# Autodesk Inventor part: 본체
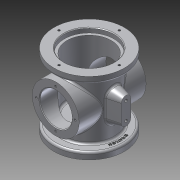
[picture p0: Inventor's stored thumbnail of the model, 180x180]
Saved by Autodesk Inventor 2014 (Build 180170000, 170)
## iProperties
Created: 2018-02
Part Number: 본체
Material: 알루미늄 6061
Document SubType Name: Modeling
Designer: OA65
Density: 2.71 g/cm^3
Appearance: 알루미늄 - 평지
Author: OA65
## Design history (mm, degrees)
sketch "스케치1"
  geometry: C1 r 33 at (0, 0); C2 r 38 at (0, 0); 1 further point
  constraints: 2 centre point, 2 coincident
  dimensions: "d0" = 66 diameter of C1; "d1" = 76 diameter of C2
extrude "돌출1" new body sketch "스케치1" distance "d2" = 108; taper "d3" = 0 deg
sketch "스케치2"
  geometry: C1 r 38 at (0, 0) reference; C2 r 52.5 at (0, 0)
  constraints: 1 centre point, 1 coincident
  dimensions: "d4" = 105 diameter of C2
extrude "돌출2" join sketch "스케치2" distance "d5" = 10; taper "d6" = 0 deg
sketch "스케치3"
  geometry: C1 r 38 at (0, 0) reference; C2 r 52.5 at (0, 0)
  constraints: 1 centre point, 1 coincident
  dimensions: "d8" = 105 diameter of C2
extrude "돌출3" join sketch "스케치3" distance "d9" = 10; taper "d10" = 0 deg
sketch "스케치4"
  geometry: C1 r 52.5 at (0, 0) reference; C2 r 37 at (0, 0)
  constraints: 1 centre point, 1 coincident
  dimensions: "d11" = 74 diameter of C2
extrude "돌출4" cut sketch "스케치4" distance "d12" = 7; taper "d13" = 0 deg
sketch "스케치5"
  geometry: C1 r 37 at (0, 0) reference; C2 r 33 at (0, 0)
  constraints: 1 centre point, 1 coincident
  dimensions: "d14" = 66 diameter of C2
extrude "돌출5" cut sketch "스케치5" distance "d15" = 79; taper "d16" = 0 deg
sketch "스케치6"
  geometry: C1 r 52.5 at (0, 0) reference; C2 r 34 at (0, 0)
  constraints: 1 centre point, 1 coincident
  dimensions: "d17" = 68 diameter of C2
extrude "돌출6" cut sketch "스케치6" distance "d18" = 16; taper "d19" = 0 deg
sketch "스케치7"
  geometry: L1 (38, 10)-(52.5, 10) reference; L2 (52.5, 10)-(52.5, 0) reference; L3 (52.5, 0)-(37, 0) reference; L4 (37, 0)-(37, 7) reference; L5 (37, 7)-(33, 7) reference; L6 (33, 7)-(33, 86) reference; L7 (33, 86)-(-33, 86) reference; L8 (-33, 86)-(-33, 7) reference; L9 (-33, 7)-(-37, 7) reference; L10 (-37, 7)-(-37, 0) reference; L11 (-37, 0)-(-52.5, 0) reference; L12 (-52.5, 0)-(-52.5, 10) reference; L13 (-52.5, 10)-(-38, 10) reference; L14 (-38, 10)-(-38, 98) reference; L15 (-38, 98)-(-52.5, 98) reference; L16 (-52.5, 98)-(-52.5, 108) reference; L17 (-52.5, 108)-(-34, 108) reference; L18 (-34, 108)-(-34, 92) reference; L19 (-34, 92)-(34, 92) reference; L20 (34, 92)-(34, 108) reference; L21 (34, 108)-(52.5, 108) reference; L22 (52.5, 108)-(52.5, 98) reference; L23 (52.5, 98)-(38, 98) reference; L24 (38, 98)-(38, 10) reference; L25 (0, 108)-(0, 54); C1 r 24 at (0, 54); C2 r 35 at (0, 54); 1 further point
  constraints: 2 centre point, 2 coincident, 2 end point, 1 parallel
  dimensions: "d20" = 54 distance of L25.start L25.end; "d21" = 48 diameter of C1; "d22" = 70 diameter of C2
extrude "돌출7" join sketch "스케치7" stored distance "d23" = 100; taper "d24" = 0 deg
sketch "스케치8"
  geometry: C1 r 24 at (0, 0) reference; C2 r 35 at (0, 0) reference; C3 r 24 at (0, 0); 1 further point
  constraints: 1 centre point, 1 coincident, 1 concentric
extrude "돌출8" cut sketch "스케치8" distance "d25" = 150; taper "d26" = 0 deg
sketch "스케치9"
  geometry: C1 r 37 at (0, 0) reference; C2 r 52.5 at (0, 0) reference; C3 r 37 at (0, 0)
  constraints: 1 centre point, 1 coincident, 1 concentric
extrude "돌출9" cut sketch "스케치9" distance "d27" = 86; taper "d28" = 0 deg
sketch "스케치10"
  geometry: C1 r 37 at (0, 0) reference; C2 r 33 at (0, 0)
  constraints: 1 centre point, 1 coincident
  dimensions: "d29" = 66 diameter of C2
extrude "돌출10" join sketch "스케치10" distance "d30" = 79; taper "d31" = 0 deg
sketch "스케치11"
  geometry: C1 r 24 at (0, 0) reference; C2 r 35 at (0, 0) reference; C3 r 24 at (0, 0); 1 further point
  constraints: 1 centre point, 1 coincident, 1 concentric
extrude "돌출11" cut sketch "스케치11" distance "d32" = 150; taper "d33" = 0 deg
sketch "스케치12"
  geometry: C1 r 33 at (0, 0) reference; C2 r 5 at (0, 0)
  constraints: 1 centre point, 1 coincident
  dimensions: "d34" = 10 diameter of C2
extrude "돌출12" cut sketch "스케치12" distance "d35" = 14; taper "d36" = 0 deg
node "작업 평면1"
fillet "모깎기1" dims "d50" = 3
fillet "모깎기2" dims "d51" = 3
chamfer "모따기1" distance "d52" = 1; stored, may be unused: second distance "d53" = 2, angle "d54" = 45 deg
sketch "스케치17" dims "d64" = 90
  geometry: C1 r 38 at (0, 0) reference; 2 further points
  constraints: 1 coincident, 1 vertical alignment, 2 other
hole "구멍2" sketch "스케치17" at (0, 45) diameter "d65" = 3.242; stored, may be unused: countersink angle "d69" = 90 deg, drill point angle "d71" = 118 deg; dims "d66" = 4, "d67" = 4, "d68" = 2, "d70" = 6
sketch "스케치18" dims "d75" = 58
  geometry: C1 r 25 at (0, 0) reference; 3 further points
  constraints: 1 coincident, 1 vertical alignment, 2 other
hole "구멍3" sketch "스케치18" at (0, 29) diameter "d76" = 3.242; stored, may be unused: countersink angle "d80" = 90 deg, drill point angle "d82" = 118 deg; dims "d77" = 4, "d78" = 4, "d79" = 2, "d81" = 6
node "작업 평면2"
sketch "스케치19"
  geometry: L1 (-31, 92)-(-5, 92) reference; L2 (-5, 92)-(-5, 86) reference; L3 (-5, 86)-(-30, 86) reference; L4 (-33, 83)-(-33, 7) reference; L5 (-33, 7)-(-37, 7) reference; L6 (-37, 7)-(-37, 1) reference; L7 (-37, 1)-(-38, 0) reference; L8 (-38, 0)-(-43.379, 0) reference; L9 (-43.379, 0)-(-43.379, 6) reference; L10 (-43.379, 6)-(-45, 6.974) reference; L11 (-45, 6.974)-(-46.621, 6) reference; L12 (-46.621, 6)-(-46.621, 0) reference; L13 (-46.621, 0)-(-52.5, 0) reference; L14 (-52.5, 0)-(-52.5, 7) reference; L15 (-49.5, 10)-(-41, 10) reference; L16 (-38, 13)-(-38, 95) reference; L17 (-41, 98)-(-49.5, 98) reference; L18 (-52.5, 101)-(-52.5, 108) reference; L19 (-52.5, 108)-(-34, 108) reference; L20 (-34, 108)-(-34, 95) reference; L21 (34, 95)-(34, 108) reference; L22 (34, 108)-(52.5, 108) reference; L23 (52.5, 108)-(52.5, 101) reference; L24 (49.5, 98)-(41, 98) reference; L25 (38, 95)-(38, 13) reference; L26 (41, 10)-(49.5, 10) reference; L27 (52.5, 7)-(52.5, 0) reference; L28 (52.5, 0)-(46.621, 0) reference; L29 (46.621, 0)-(46.621, 6) reference; L30 (46.621, 6)-(45, 6.974) reference; L31 (45, 6.974)-(43.379, 6) reference; L32 (43.379, 6)-(43.379, 0) reference; L33 (43.379, 0)-(38, 0) reference; L34 (38, 0)-(37, 1) reference; L35 (37, 1)-(37, 7) reference; L36 (37, 7)-(33, 7) reference; L37 (33, 7)-(33, 83) reference; L38 (30, 86)-(5, 86) reference; L39 (5, 86)-(5, 92) reference; L40 (5, 92)-(31, 92) reference; L41 (0, 54)-(55, 54); L42 (55, 41)-(55, 34); L43 (55, 34)-(38, 29.445); L44 (55, 67)-(55, 74); L45 (55, 74)-(38, 78.555); L46 (55, 41)-(38, 41); L47 (55, 67)-(38, 67); A1 r 3 centre (-31, 95) between (-34, 95) and (-31, 92) reference; A2 r 3 centre (-30, 83) between (-30, 86) and (-33, 83) reference; A3 r 3 centre (-49.5, 7) between (-49.5, 10) and (-52.5, 7) reference; A4 r 3 centre (-41, 13) between (-41, 10) and (-38, 13) reference; A5 r 3 centre (-41, 95) between (-38, 95) and (-41, 98) reference; A6 r 3 centre (-49.5, 101) between (-52.5, 101) and (-49.5, 98) reference; A7 r 3 centre (31, 95) between (31, 92) and (34, 95) reference; A8 r 3 centre (49.5, 101) between (49.5, 98) and (52.5, 101) reference; A9 r 3 centre (41, 95) between (41, 98) and (38, 95) reference; A10 r 3 centre (41, 13) between (38, 13) and (41, 10) reference; A11 r 3 centre (49.5, 7) between (52.5, 7) and (49.5, 10) reference; A12 r 3 centre (30, 83) between (33, 83) and (30, 86) reference; 2 further points
  constraints: 14 end point, 4 point on line, 3 perpendicular, 1 collinear, 1 parallel, 1 other
  dimensions: "d87" = 55 distance of L41.start L41.end; "d88" = 20 distance of L41.end L42.end; "d89" = 20 distance of L41.end L44.end; "d90" = 13 distance of L42.start L41.end; "d91" = 13 distance of L44.start L41.end
  node "절단 모서리 투영4"
revolve "회전3" stored, may be unused: angle "d92" = 90 deg
revolve "회전4" stored, may be unused: angle "d93" = 90 deg
sketch "스케치20"
  geometry: L1 (-7, 0)-(-7, -26); L2 (7, 0)-(7, -26); A1 r 7 centre (0, 0) between (-7, 0) and (7, 0) reference; A2 r 7 centre (0, -26) between (-7, -26) and (7, -26) reference; A3 r 7 centre (0, 0) between (-7, 0) and (7, 0) reference; 1 further point
  constraints: 6 point on circle, 4 end point, 4 tangent
extrude "돌출15" join sketch "스케치20" stored distance "d94" = 15; taper "d95" = 15 deg
fillet "모깎기3" dims "d96" = 3
sketch "스케치21"
  geometry: A1 r 7 centre (-7, 0) between (-14, 0) and (0, 0) reference; A2 r 7 centre (-7, 26) between (0, 26) and (-14, 26) reference; 3 further points
  constraints: 2 coincident
hole "구멍4" sketch "스케치21" at (-7, 26), (-7, 0) diameter "d97" = 4.134; stored, may be unused: countersink angle "d101" = 90 deg, drill point angle "d103" = 118 deg; dims "d98" = 6, "d99" = 4, "d100" = 2, "d102" = 8
sketch "스케치22" dims "d104" = 86
  geometry: L1 (0, 0)-(0, 43); C1 r 41 at (0, 0) reference
  constraints: 2 end point, 1 coincident, 1 vertical, 1 vertical alignment, 2 other
feature "엠보싱1" sketch "스케치22" dims "d0" = 66, "d1" = 76, "d105" = 0.5, "d106" = 0
node "솔리드1"
pattern_circular "원형 패턴1" dims angle "d73" = 360 deg
pattern_circular "원형 패턴2" dims angle "d84" = 360 deg
mirror "대칭3"
node "절단 모서리 투영1"
node "절단 모서리 투영5"
other parameters: "d49" = 0, "d86" = 0
